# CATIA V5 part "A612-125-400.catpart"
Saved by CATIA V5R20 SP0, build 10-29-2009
Part number: A612-125-400
Source: Unknown
Property "A": "30.000"
Property "ARTICLENO": "A612-125-400"
Property "B": "50.000"
Property "BOMINFO": "A612-125-400"
Property "CODE": "A612-125-400"
Property "D": "22.000"
Property "FORM": "C"
Property "L": "400.000"
Property "L1": "45.000"
Property "L2": "80.000"
Property "L3": "75.000"
Property "LINA": "A612-125-400"
Property "NB": "A612-125-400"
Property "NBSYN": "$CODE."
Property "NN": "A612"
Property "NT": "CDI 3357 E-Type Wear Plates, steel and self-lubricating"
Property "SUPPLIER": "CF"
Property "T": "30.000"
Property "W": "125.000"
Bounding box of the stored display mesh (mm): x 0 to 30, y 0 to 400, z 0 to 125
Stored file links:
  C:\Users\Utente\Desktop\3D files A612\A612-125-400.catpart
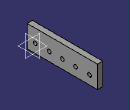
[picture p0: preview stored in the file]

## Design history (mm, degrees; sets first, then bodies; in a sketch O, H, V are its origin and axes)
Body1 "Geometry.1" (main body)
  Solid1 "A612-125-400.catpart": solid without history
